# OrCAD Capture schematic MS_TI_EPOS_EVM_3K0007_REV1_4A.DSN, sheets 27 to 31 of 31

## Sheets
27 Pg06: NAND Flash Memory: size C
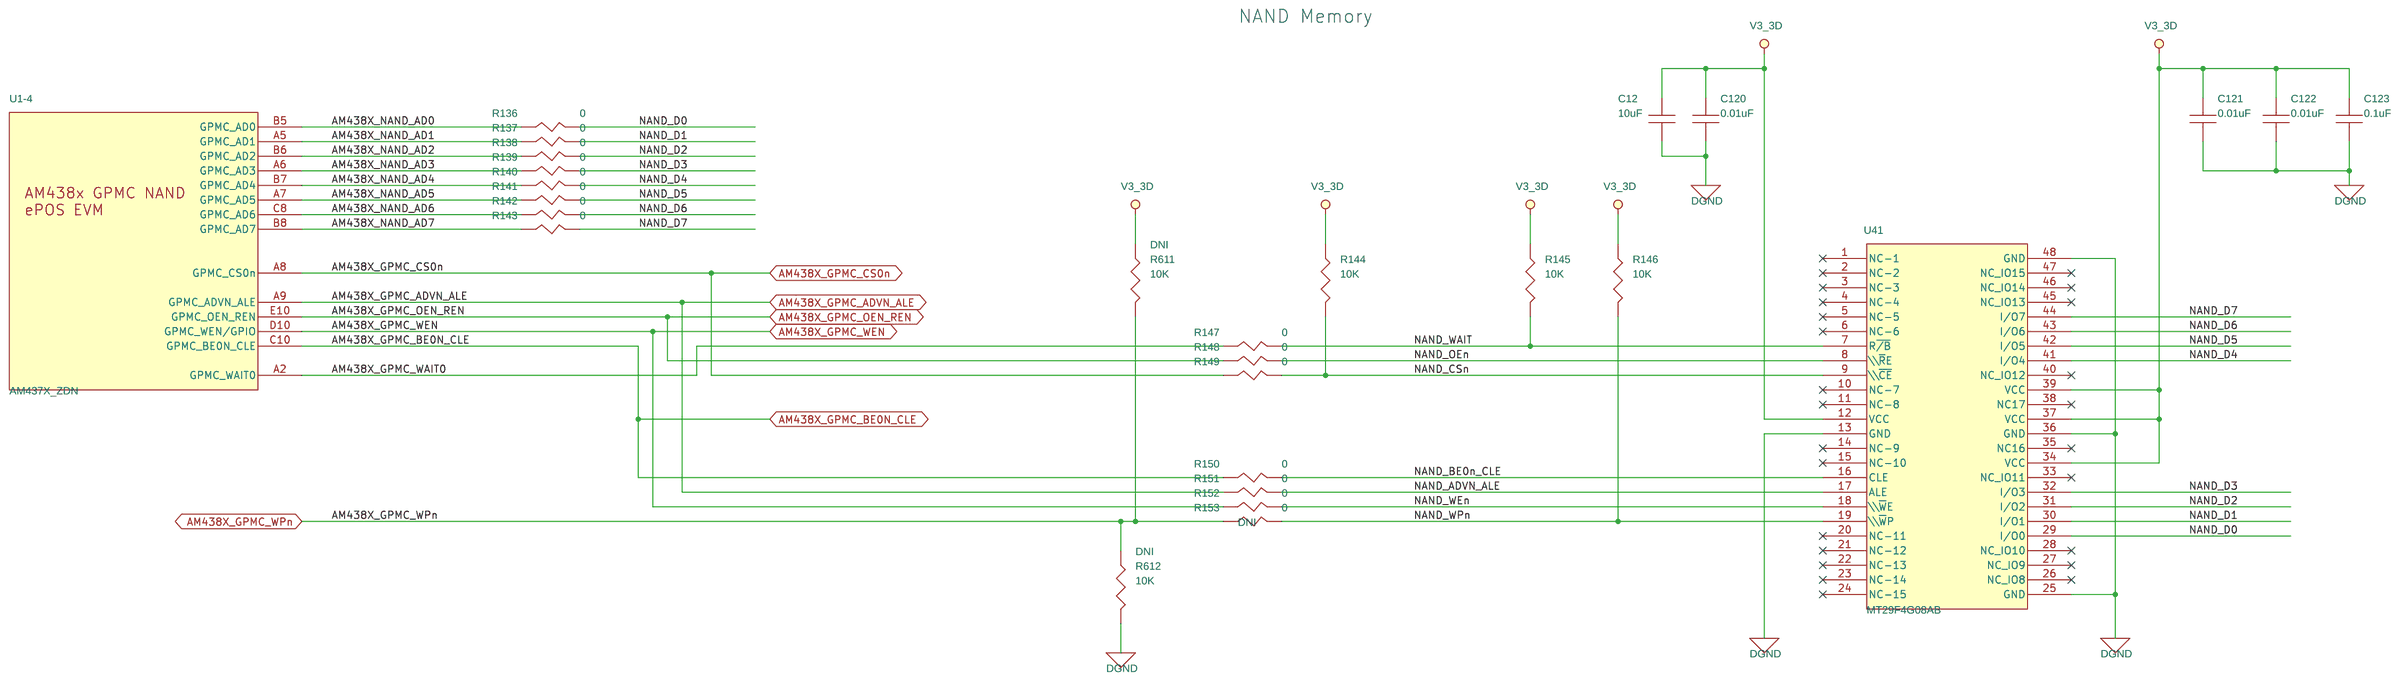
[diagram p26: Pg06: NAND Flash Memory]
28 Pg28: Unused pins/GPIO: size C
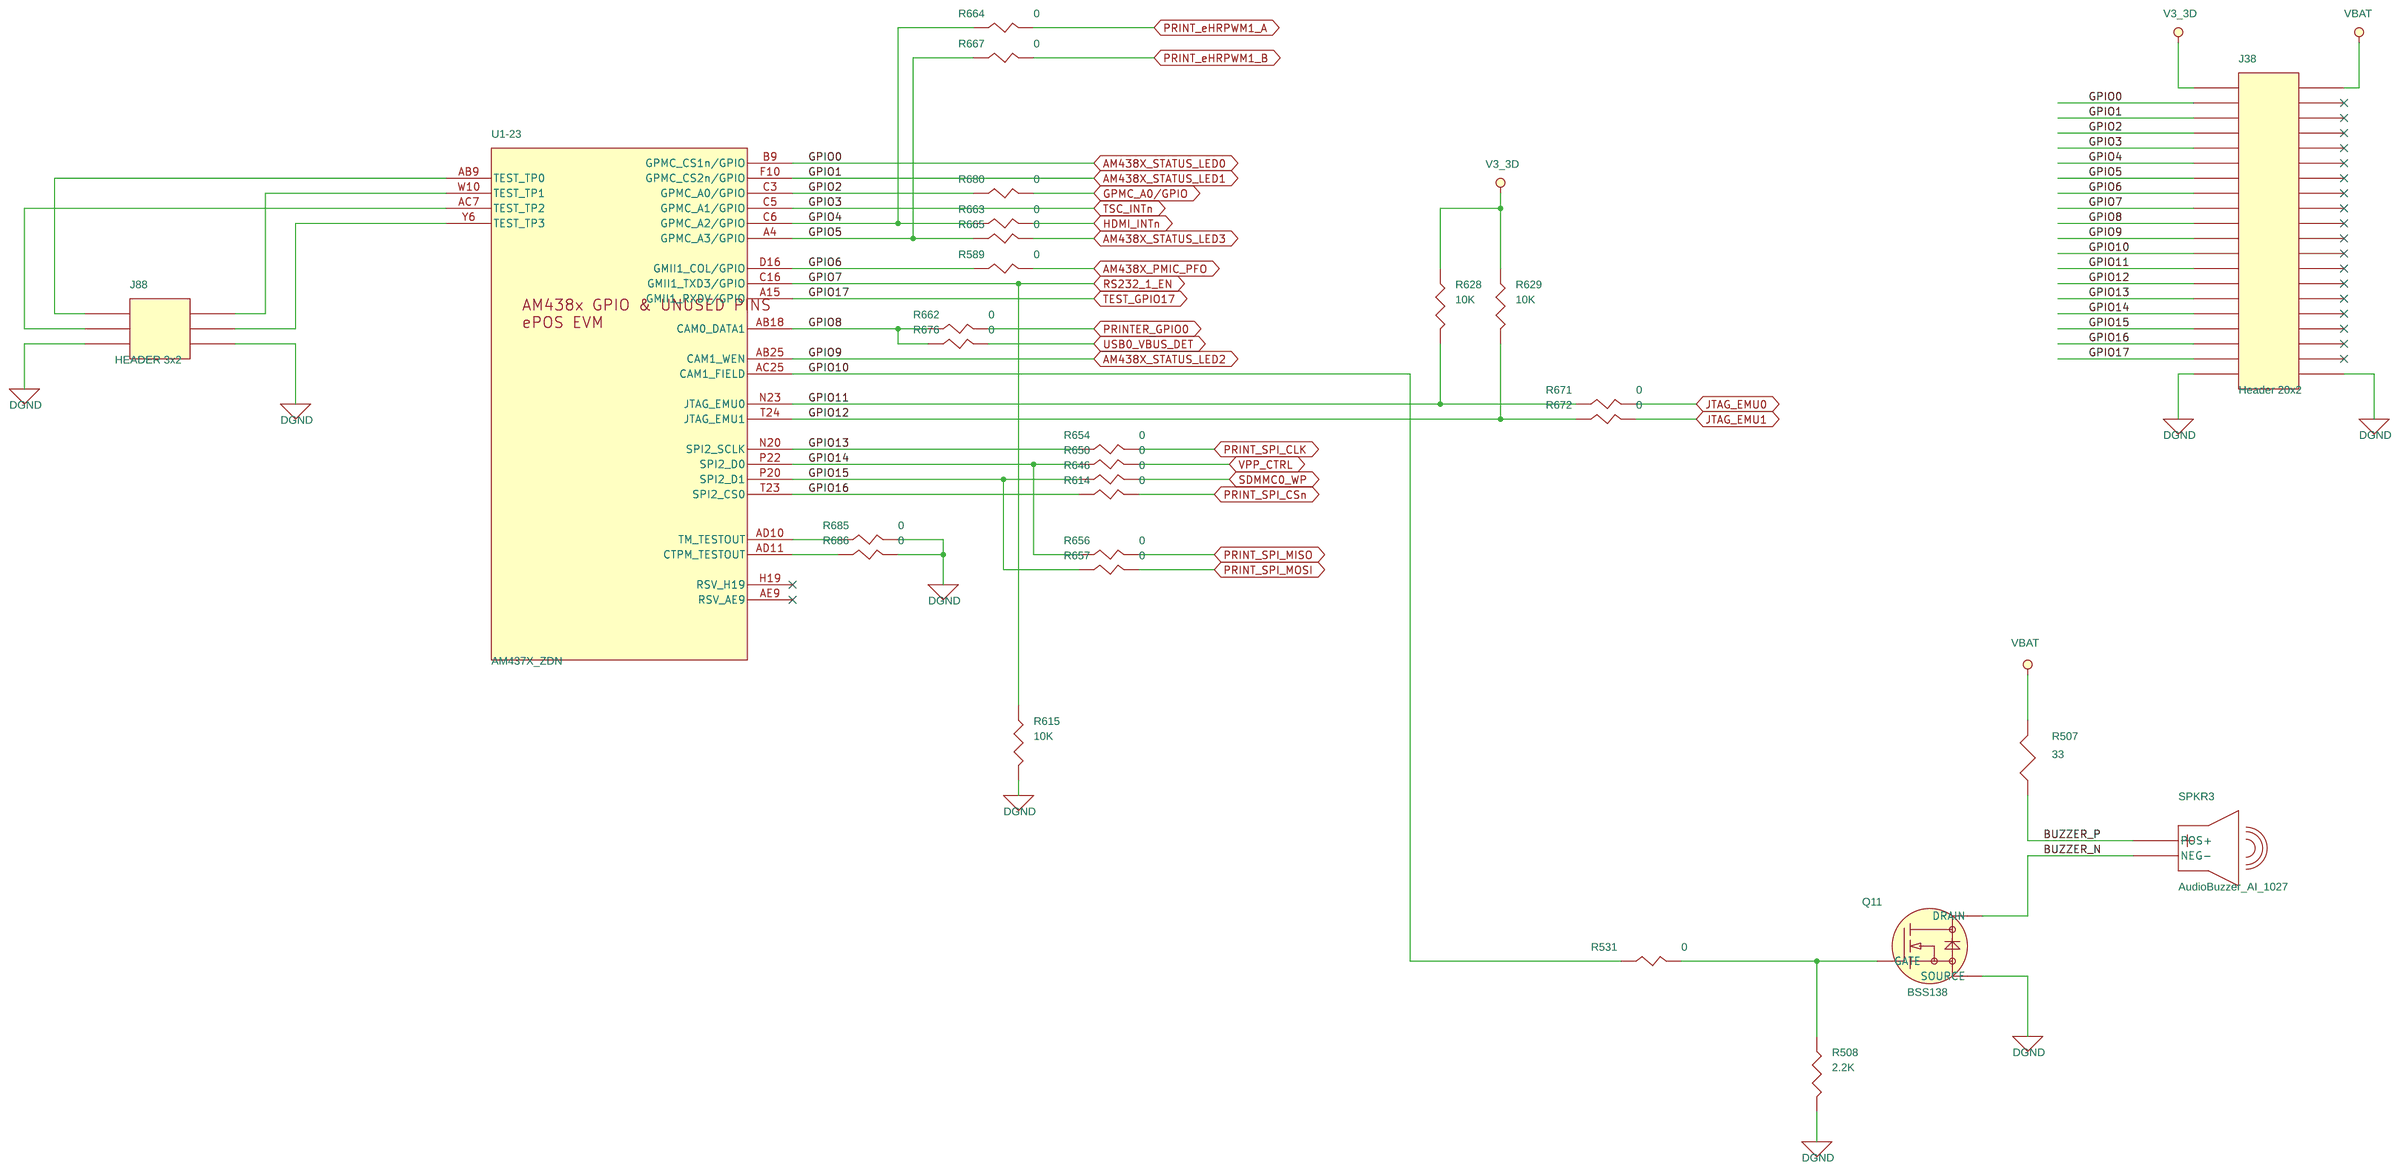
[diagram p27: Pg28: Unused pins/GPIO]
29 Pg31: Hardware schematics
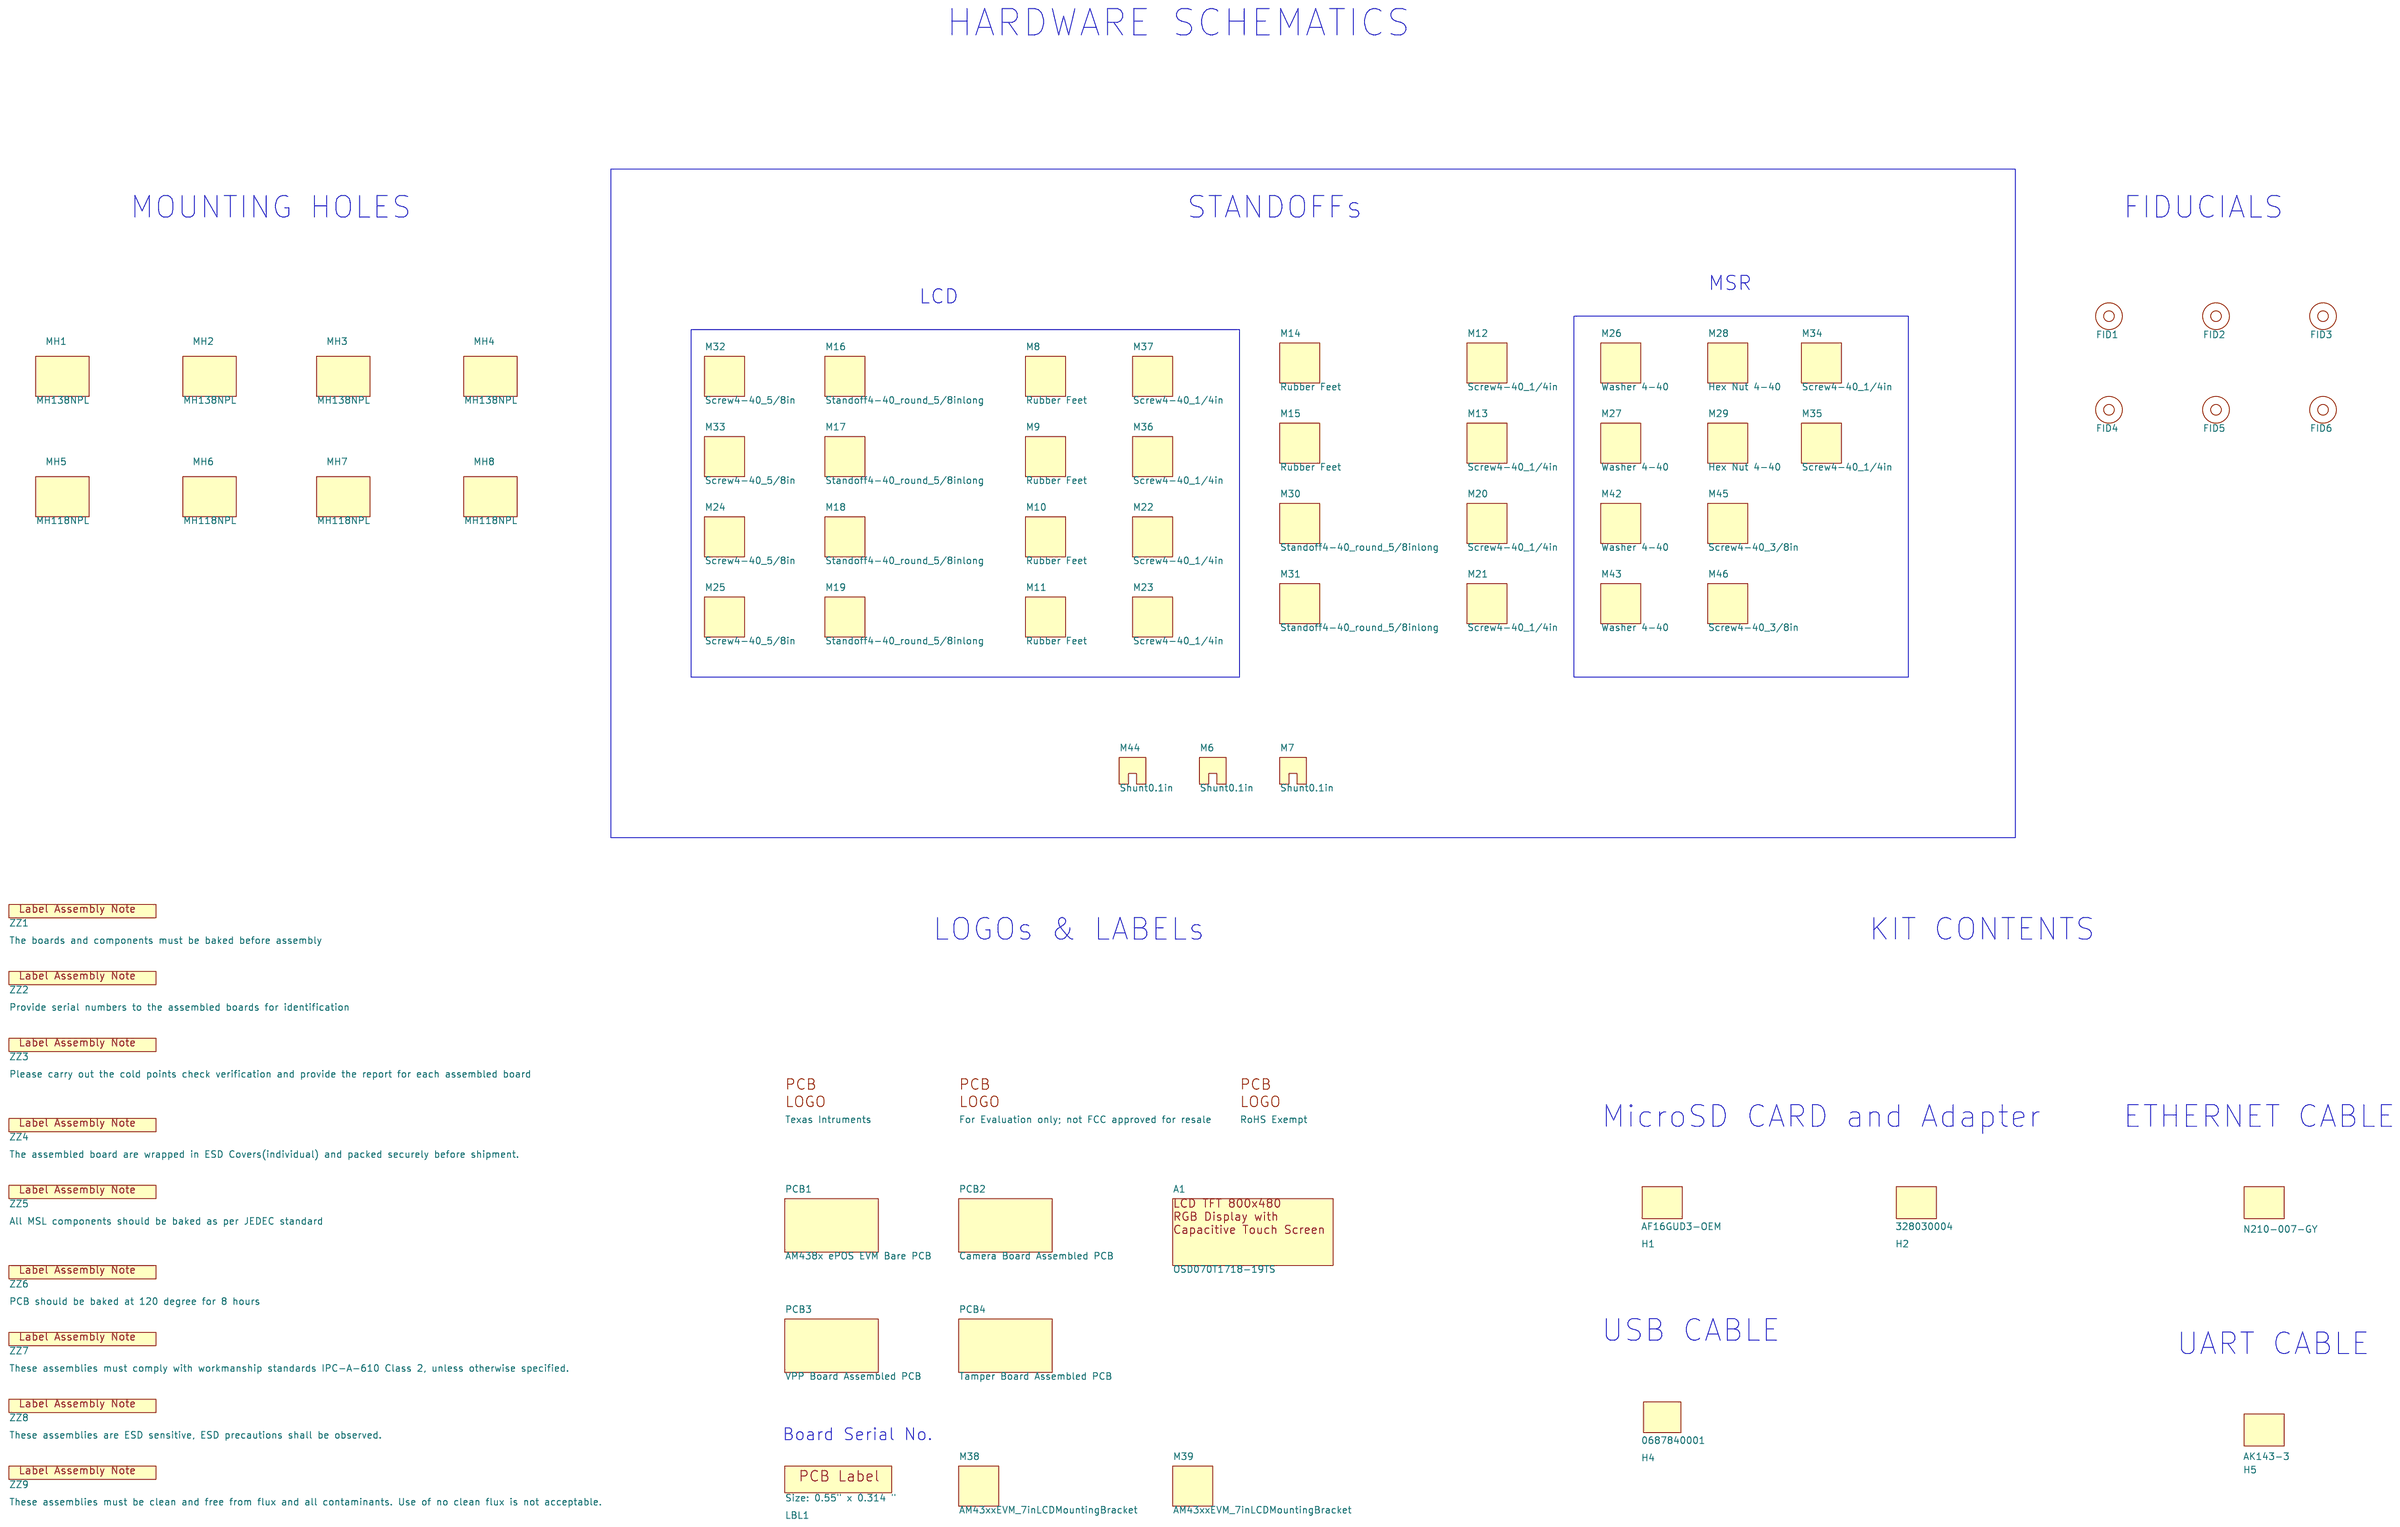
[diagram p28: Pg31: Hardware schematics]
30 Pg04: Power Supply - PMIC: size C
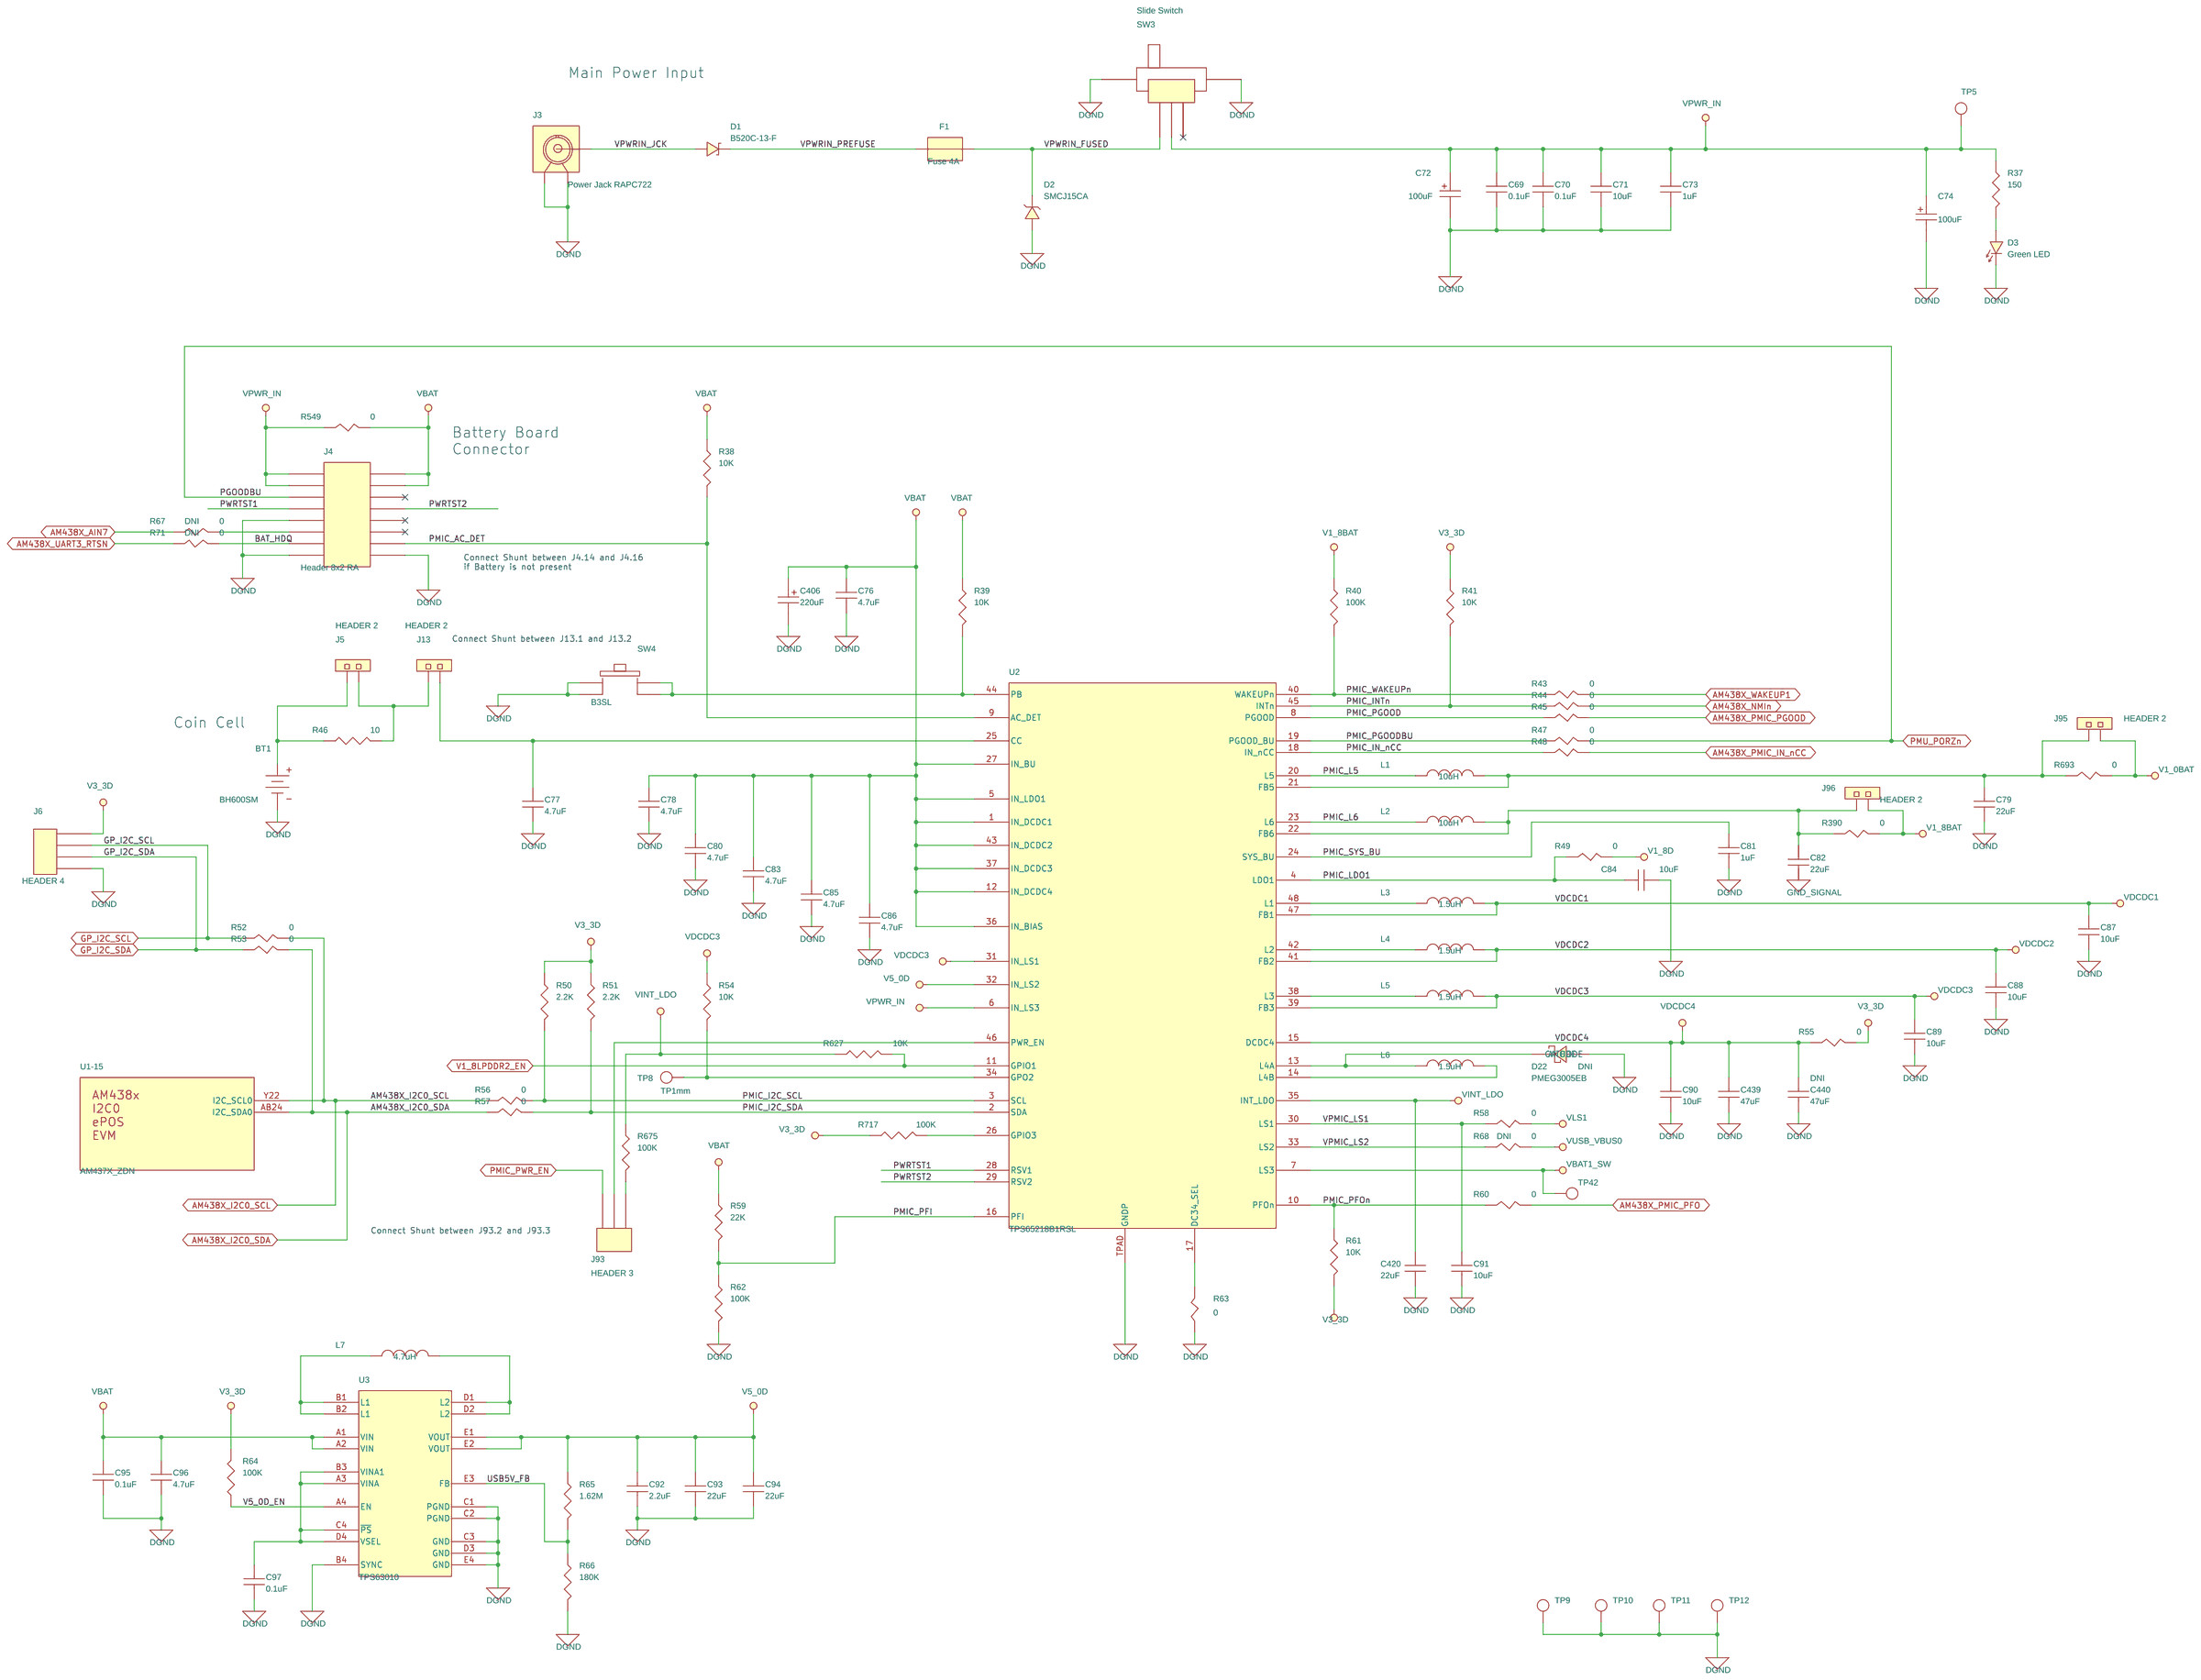
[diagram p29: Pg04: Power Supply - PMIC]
31 Pg02: Processor subsystem/RTC: size C
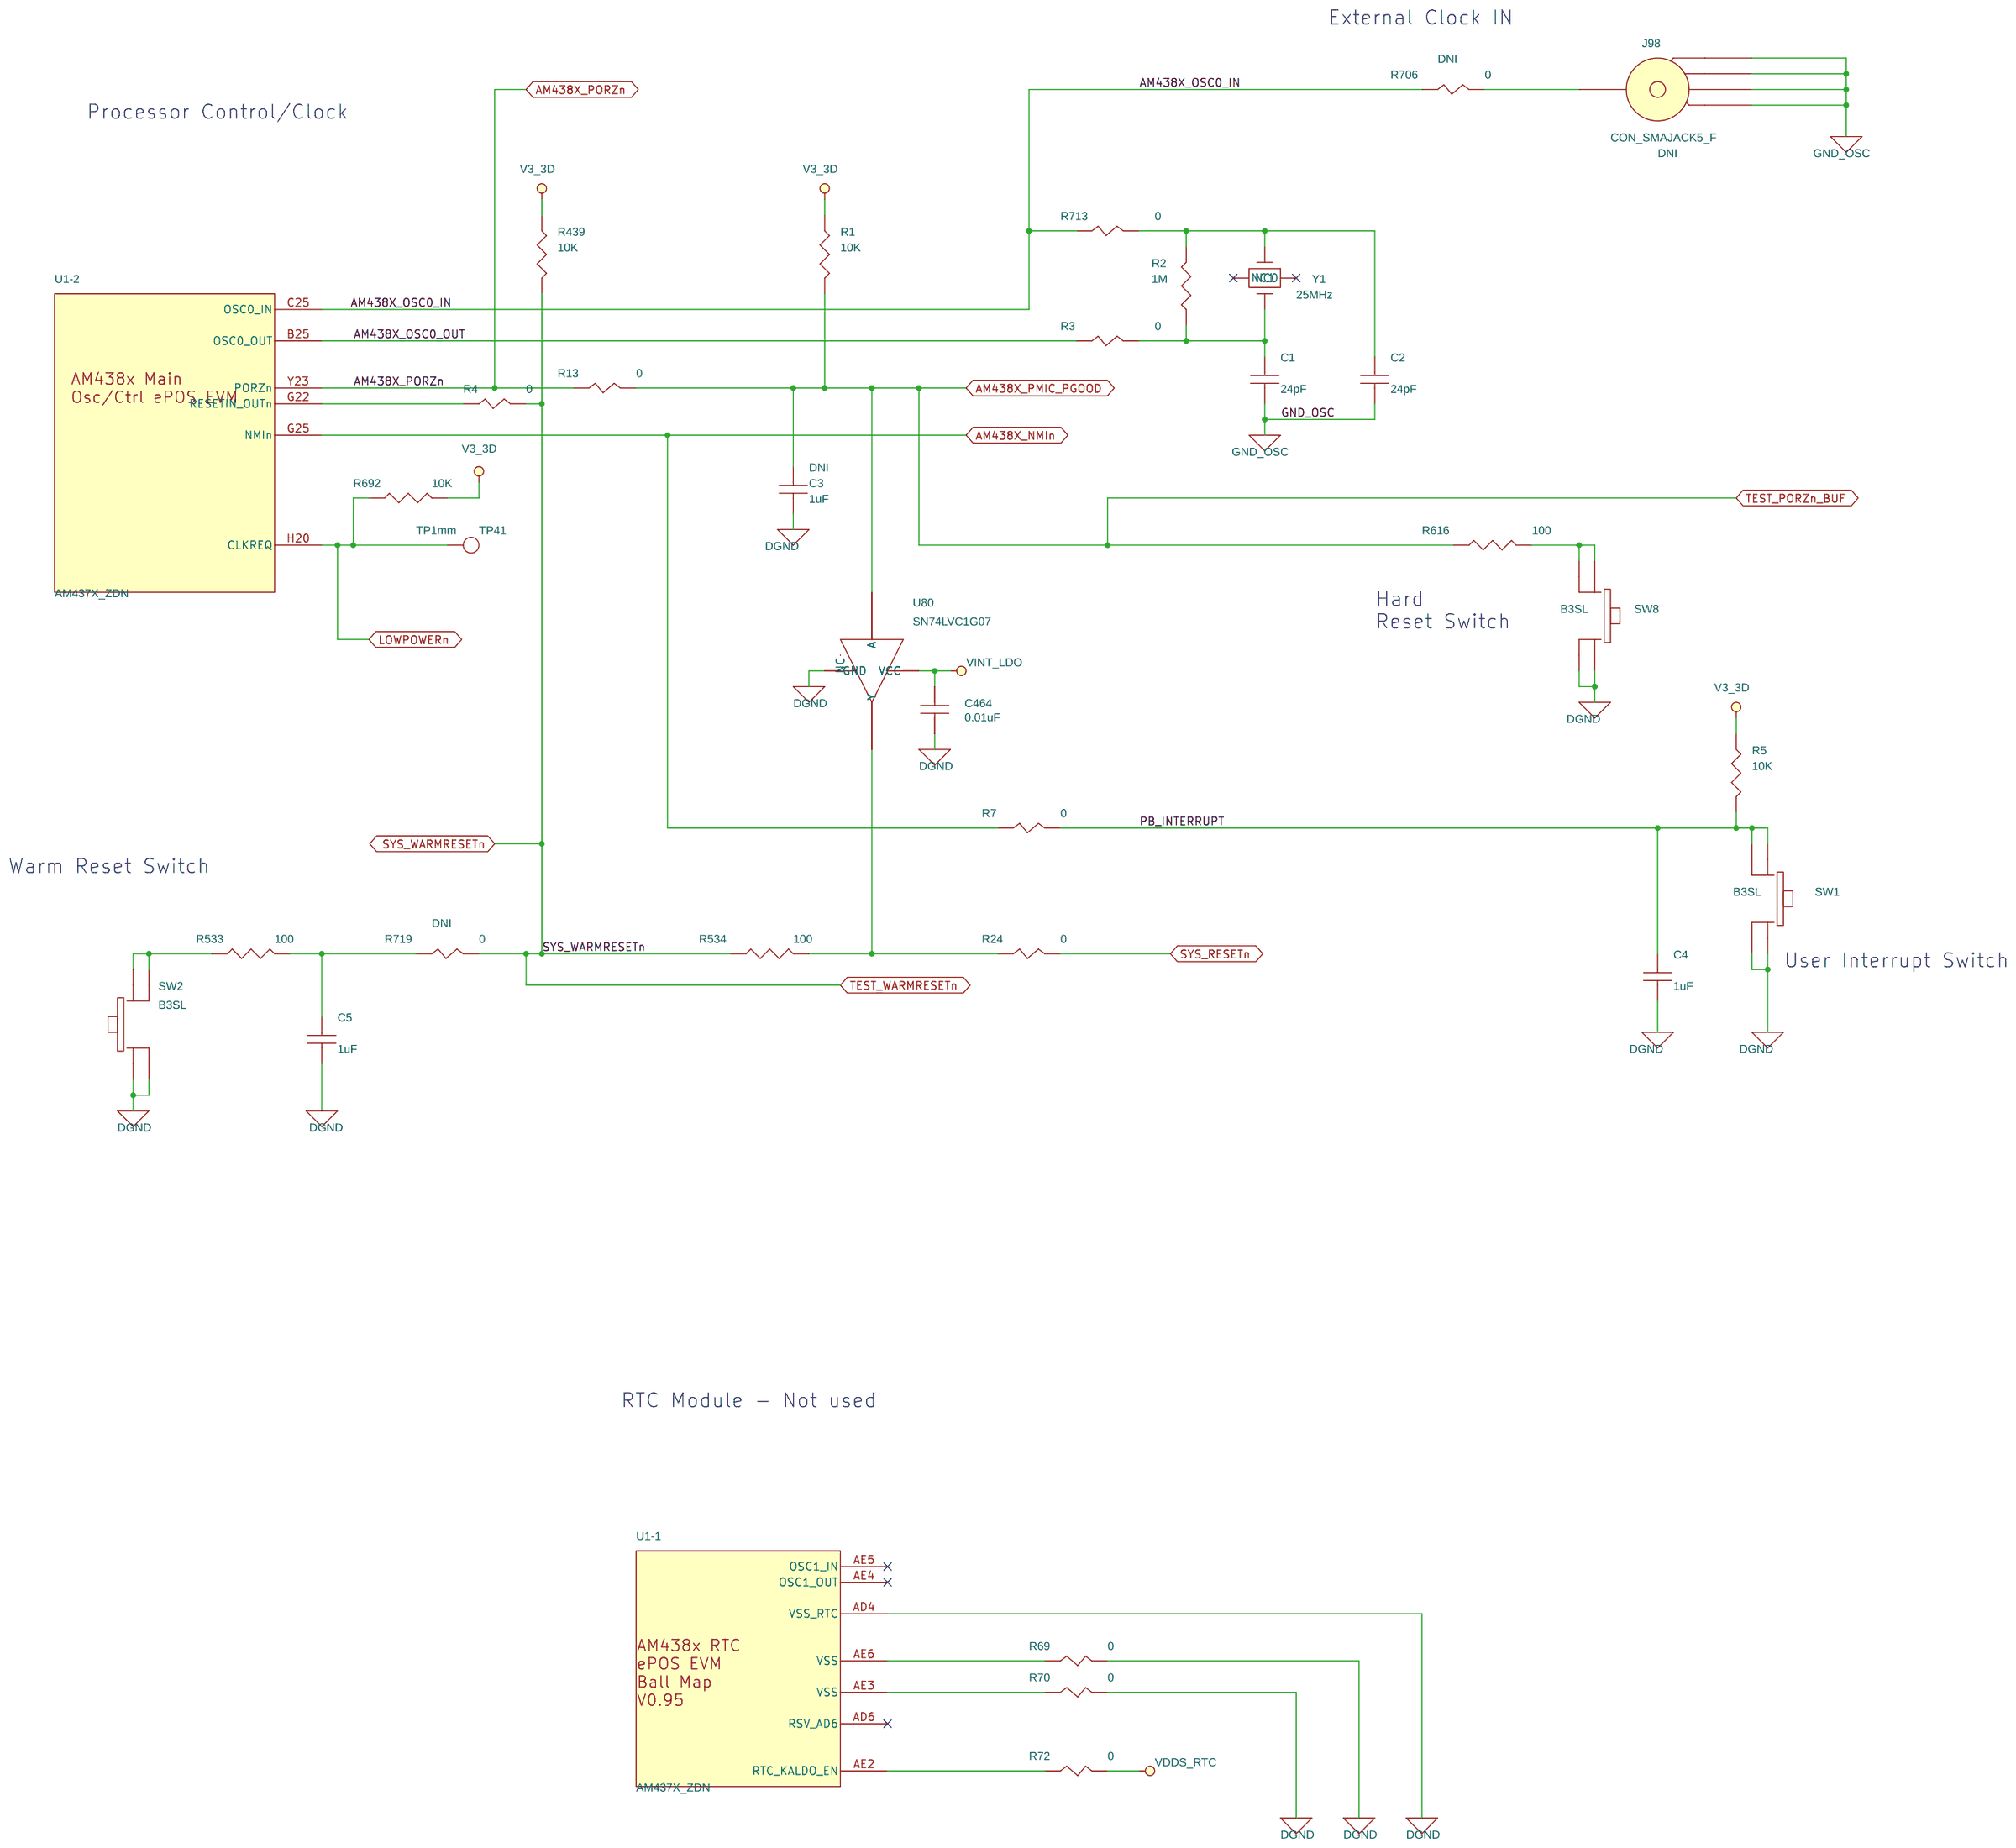
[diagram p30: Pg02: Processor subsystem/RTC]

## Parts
sheet Pg02: Processor subsystem/RTC
C1  24pF  [SM-7351-CAP-0402]
C2  24pF  [SM-7351-CAP-0402]
C3  1uF  [SM-7351-CAP-0402]
C4  1uF  [SM-7351-CAP-0402]
C5  1uF  [SM-7351-CAP-0402]
C464  0.01uF  [SM-7351-CAP-0402]
J98  CON_SMAJACK5_F  [CON_SMAJACK5_221789-1_S_S_T]
R1  10K  [SM-7351-RES-0402]
R2  1M  [SM-7351-RES-0402]
R3  0  [SM-7351-RES-0402]
R4  0  [SM-7351-RES-0402]
R5  10K  [SM-7351-RES-0402]
R7  0  [SM-7351-RES-0402]
R13  0  [SM-7351-RES-0402]
R24  0  [SM-7351-RES-0402]
R69  0  [SM-7351-RES-0402]
R70  0  [SM-7351-RES-0402]
R72  0  [SM-7351-RES-0402]
R439  10K  [SM-7351-RES-0402]
R533  100  [SM-7351-RES-0402]
R534  100  [SM-7351-RES-0402]
R616  100  [SM-7351-RES-0402]
R692  10K  [SM-7351-RES-0402]
R706  0  [SM-7351-RES-0402]
R713  0  [SM-7351-RES-0402]
R719  0  [SM-7351-RES-0402]
SW1  B3SL  [SW_B3SL-1022P]
SW2  B3SL  [SW_B3SL-1022P]
SW8  B3SL  [SW_B3SL-1022P]
TP41  TP1mm  [tp_smd1mmcircle]
U80  SN74LVC1G07  [SC70-5-43M]
Y1  25MHz  [XTAL2x3-30m]
sheet Pg04: Power Supply - PMIC
BT1  BH600SM  [bh600sm]
C69  0.1uF  [SM-7351-CAP-0402]
C70  0.1uF  [SM-7351-CAP-0402]
C71  10uF  [SM-7351-CAP-0805]
C72  100uF  [SM-7351-CAP-smdcan]
C73  1uF  [SM-7351-CAP-0603]
C74  100uF  [SM-7351-CAP-smdcan]
C76  4.7uF  [SM-7351-CAP-0603]
C77  4.7uF  [SM-7351-CAP-0603]
C78  4.7uF  [SM-7351-CAP-0603]
C79  22uF  [SM-7351-CAP-0603]
C80  4.7uF  [SM-7351-CAP-0603]
C81  1uF  [SM-7351-CAP-0402]
C82  22uF  [SM-7351-CAP-0603]
C83  4.7uF  [SM-7351-CAP-0603]
C84  10uF  [SM-7351-CAP-0805]
C85  4.7uF  [SM-7351-CAP-0603]
C86  4.7uF  [SM-7351-CAP-0603]
C87  10uF  [SM-7351-CAP-0805]
C88  10uF  [SM-7351-CAP-0805]
C89  10uF  [SM-7351-CAP-0805]
C90  10uF  [SM-7351-CAP-0805]
C91  10uF  [SM-7351-CAP-0805]
C92  2.2uF  [SM-7351-CAP-0402]
C93  22uF  [SM-7351-CAP-0805]
C94  22uF  [SM-7351-CAP-0805]
C95  0.1uF  [SM-7351-CAP-0402]
C96  4.7uF  [SM-7351-CAP-0603]
C97  0.1uF  [SM-7351-CAP-0402]
C406  220uF  [smd7343-122m]
C420  22uF  [SM-7351-CAP-0805]
C439  47uF  [SM-7351-CAP-1206]
C440  47uF  [SM-7351-CAP-1206]
D1  B520C-13-F  [B520C-13-F]
D2  SMCJ15CA  [SMCJ15CA]
D3  Green LED  [sm_led_0805]
D22  PMEG3005EB  [DIO_SOD523]
F1  Fuse 4A  [smdfuseblk]
J3  Power Jack RAPC722  [RAPC712]
J4  Header 8x2 RA  [HDR2X8RA-201M]
J5  HEADER 2  [header_2x1]
J6  HEADER 4  [HDR1x4-330M]
J13  HEADER 2  [header_2x1]
J93  HEADER 3  [header_3x1]
J95  HEADER 2  [header_2x1]
J96  HEADER 2  [header_2x1]
L1  10uH  [ind-mlz2012-57m]
L2  10uH  [ind-mlz2012-57m]
L3  1.5uH  [IND_SPM3012T]
L4  1.5uH  [IND_SPM3012T]
L5  1.5uH  [IND_SPM3012T]
L6  1.5uH  [IND_SPM3012T]
L7  4.7uH  [smd_slf7055t]
R37  150  [SM-7351-RES-0402]
R38  10K  [SM-7351-RES-0402]
R39  10K  [SM-7351-RES-0402]
R40  100K  [SM-7351-RES-0402]
R41  10K  [SM-7351-RES-0402]
R43  0  [SM-7351-RES-0402]
R44  0  [SM-7351-RES-0402]
R45  0  [SM-7351-RES-0402]
R46  10  [SM-7351-RES-0402]
R47  0  [SM-7351-RES-0402]
R48  0  [SM-7351-RES-0402]
R49  0  [SM-7351-RES-0603]
R50  2.2K  [sm-7351-res-0402]
R51  2.2K  [sm-7351-res-0402]
R52  0  [SM-7351-RES-0402]
R53  0  [SM-7351-RES-0402]
R54  10K  [SM-7351-RES-0402]
R55  0  [SM-7351-RES-0603]
R56  0  [SM-7351-RES-0402]
R57  0  [SM-7351-RES-0402]
R58  0  [SM-7351-RES-0402]
R59  22K  [SM-7351-RES-0402]
R60  0  [SM-7351-RES-0402]
R61  10K  [SM-7351-RES-0402]
R62  100K  [SM-7351-RES-0402]
R63  0  [SM-7351-RES-0402]
R64  100K  [SM-7351-RES-0402]
R65  1.62M  [SM-7351-RES-0402]
R66  180K  [SM-7351-RES-0402]
R67  0  [SM-7351-RES-0402]
R68  0  [SM-7351-RES-0402]
R71  0  [SM-7351-RES-0402]
R390  0  [SM-7351-RES-0603]
R549  0  [SM-7351-RES-1210]
R627  10K  [SM-7351-RES-0402]
R675  100K  [SM-7351-RES-0402]
R693  0  [SM-7351-RES-0603]
R717  100K  [SM-7351-RES-0402]
SW3  Slide Switch  [TH_SW_T551101]
SW4  B3SL  [SW_B3SL-1022P]
TP5  TP  [TH_TP_5002]
TP8  TP1mm  [tp_smd1mmcircle]
TP9  TP  [TH_TP_5002]
TP10  TP  [TH_TP_5002]
TP11  TP  [TH_TP_5002]
TP12  TP  [TH_TP_5002]
TP42  TP  [TH_TP_5002]
U2  TPS65218B1RSL  [qfn6x6-48-39m]
U3  TPS63010  [u_20_dsbga]
sheet Pg06: NAND Flash Memory
C12  10uF  [SM-7351-CAP-0805]
C120  0.01uF  [SM-7351-CAP-0402]
C121  0.01uF  [SM-7351-CAP-0402]
C122  0.01uF  [SM-7351-CAP-0402]
C123  0.1uF  [SM-7351-CAP-0402]
R136  0  [SM-7351-RES-0402]
R137  0  [SM-7351-RES-0402]
R138  0  [SM-7351-RES-0402]
R139  0  [SM-7351-RES-0402]
R140  0  [SM-7351-RES-0402]
R141  0  [SM-7351-RES-0402]
R142  0  [SM-7351-RES-0402]
R143  0  [SM-7351-RES-0402]
R144  10K  [SM-7351-RES-0402]
R145  10K  [SM-7351-RES-0402]
R146  10K  [SM-7351-RES-0402]
R147  0  [SM-7351-RES-0402]
R148  0  [SM-7351-RES-0402]
R149  0  [SM-7351-RES-0402]
R150  0  [SM-7351-RES-0402]
R151  0  [SM-7351-RES-0402]
R152  0  [SM-7351-RES-0402]
R153  0  [SM-7351-RES-0402]
R611  10K  [SM-7351-RES-0402]
R612  10K  [SM-7351-RES-0402]
U41  MT29F4G08AB  [skt-tsop48sm]
sheet Pg26: Keypad/LED's
U1  AM437X_ZDN  [AM437X_ZDN]  (sections -1,-10,-11,-12,-13,-14,-15,-16,-17,-18,-19,-2,-20,-21,-22,-23,-24,-25,-26,-27,-3,-4,-5,-6,-7,-8,-9)
sheet Pg28: Unused pins/GPIO
J38  Header 20x2  [HDR2X20-330M]
J88  HEADER 3x2  [hdr2x3-330m]
Q11  BSS138  [SOT23-3]
R507  33  [SM-7351-RES-0402]
R508  2.2K  [sm-7351-res-0402]
R531  0  [SM-7351-RES-0402]
R589  0  [SM-7351-RES-0402]
R614  0  [SM-7351-RES-0402]
R615  10K  [SM-7351-RES-0402]
R628  10K  [SM-7351-RES-0402]
R629  10K  [SM-7351-RES-0402]
R646  0  [SM-7351-RES-0402]
R650  0  [SM-7351-RES-0402]
R654  0  [SM-7351-RES-0402]
R656  0  [SM-7351-RES-0402]
R657  0  [SM-7351-RES-0402]
R662  0  [SM-7351-RES-0402]
R663  0  [SM-7351-RES-0402]
R664  0  [SM-7351-RES-0402]
R665  0  [SM-7351-RES-0402]
R667  0  [SM-7351-RES-0402]
R671  0  [SM-7351-RES-0402]
R672  0  [SM-7351-RES-0402]
R676  0  [SM-7351-RES-0402]
R680  0  [SM-7351-RES-0402]
R685  0  [SM-7351-RES-0402]
R686  0  [SM-7351-RES-0402]
SPKR3  AudioBuzzer_AI_1027  [spkr_ai_1027]
sheet Pg31: Hardware schematics
A1  OSD070T1718-19TS  [DNP]
FID1  Fiducial  [Fiducial10-20]
FID2  Fiducial  [Fiducial10-20]
FID3  Fiducial  [Fiducial10-20]
FID4  Fiducial  [Fiducial10-20]
FID5  Fiducial  [Fiducial10-20]
FID6  Fiducial  [Fiducial10-20]
H1  AF16GUD3-OEM  [Keystone_1902C]
H2  328030004  [Keystone_1902C]
H3  N210-007-GY  [Keystone_1902C]
H4  0687840001  [Keystone_1902C]
H5  AK143-3  [Keystone_1902C]
LBL1  Size: 0.55" x 0.314 "  [Label_650x200]
LOGO1  Texas Intruments  [TI_Stacked_Overlay_Small]
LOGO3  For Evaluation only; not FCC approved for resale  [FCC_disclaimer]
LOGO4  RoHS Exempt  [TI_Stacked_Overlay_Small]
M6  Shunt0.1in  [DNP]
M7  Shunt0.1in  [DNP]
M8  Rubber Feet  [DNP]
M9  Rubber Feet  [DNP]
M10  Rubber Feet  [DNP]
M11  Rubber Feet  [DNP]
M12  Screw4-40_1/4in  [DNP]
M13  Screw4-40_1/4in  [DNP]
M14  Rubber Feet  [DNP]
M15  Rubber Feet  [DNP]
M16  Standoff4-40_round_5/8inlong  [DNP]
M17  Standoff4-40_round_5/8inlong  [DNP]
M18  Standoff4-40_round_5/8inlong  [DNP]
M19  Standoff4-40_round_5/8inlong  [DNP]
M20  Screw4-40_1/4in  [DNP]
M21  Screw4-40_1/4in  [DNP]
M22  Screw4-40_1/4in  [DNP]
M23  Screw4-40_1/4in  [DNP]
M24  Screw4-40_5/8in  [DNP]
M25  Screw4-40_5/8in  [DNP]
M26  Washer 4-40  [DNP]
M27  Washer 4-40  [DNP]
M28  Hex Nut 4-40  [DNP]
M29  Hex Nut 4-40  [DNP]
M30  Standoff4-40_round_5/8inlong  [DNP]
M31  Standoff4-40_round_5/8inlong  [DNP]
M32  Screw4-40_5/8in  [DNP]
M33  Screw4-40_5/8in  [DNP]
M34  Screw4-40_1/4in  [DNP]
M35  Screw4-40_1/4in  [DNP]
M36  Screw4-40_1/4in  [DNP]
M37  Screw4-40_1/4in  [DNP]
M38  AM43xxEVM_7inLCDMountingBracket  [DNP]
M39  AM43xxEVM_7inLCDMountingBracket  [DNP]
M42  Washer 4-40  [DNP]
M43  Washer 4-40  [DNP]
M44  Shunt0.1in  [DNP]
M45  Screw4-40_3/8in  [DNP]
M46  Screw4-40_3/8in  [DNP]
MH1  MH138NPL
MH2  MH138NPL
MH3  MH138NPL
MH4  MH138NPL
MH5  MH118NPL
MH6  MH118NPL
MH7  MH118NPL
MH8  MH118NPL
PCB1  AM438x ePOS EVM Bare PCB  [DNP]
PCB2  Camera Board Assembled PCB  [DNP]
PCB3  VPP Board Assembled PCB
PCB4  Tamper Board Assembled PCB
ZZ1  The boards and components must be baked before assembly  [AssemblyNoteLabel]
ZZ2  Provide serial numbers to the assembled boards for identification  [AssemblyNoteLabel]
ZZ3  Please carry out the cold points check verification and provide the report for each assembled board  [AssemblyNoteLabel]
ZZ4  The assembled board are wrapped in ESD Covers(individual) and packed securely before shipment.  [AssemblyNoteLabel]
ZZ5  All MSL components should be baked as per JEDEC standard  [AssemblyNoteLabel]
ZZ6  PCB should be baked at 120 degree for 8 hours  [AssemblyNoteLabel]
ZZ7  These assemblies must comply with workmanship standards IPC-A-610 Class 2, unless otherwise specified.  [AssemblyNoteLabel]
ZZ8  These assemblies are ESD sensitive, ESD precautions shall be observed.  [AssemblyNoteLabel]
ZZ9  These assemblies must be clean and free from flux and all contaminants. Use of no clean flux is not acceptable.  [AssemblyNoteLabel]

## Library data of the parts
C1 C2 = 1C_24pFCapacitor50V5%SMD0402: Cost100: 0.16; Cost10K: 0; Mistral Part No: M120016080001
C3 = 1C_1uFCapacitor10V10%0402: Cost100: 0.33; Cost10K: 0.2; Loading: DNI; Mistral Part No: 120014050010-R
C4 C5 C81 = 1C_1uFCapacitor10V10%0402: Cost100: 0.33; Cost10K: 0.2; Mistral Part No: 120014050010-R
C120-C122 C464 = 1C_0.01uFCapacitor16V10%0402: Cost100: 0; Cost10K: 0.01; Mistral Part No: 120009030032-R
J98 = CON_SMAJACK5_F: Chkd/date: NAVEED/031014; Composition: Updated drill size; Crtd /date: VASANTHA/240714; Custom_Duty: 24%; Customs_HS_Code: 85369090; DescriptiveText: CON SMA JACK 5POS FEMALE ST TH; Distributor_name: DIGIKEY; Distributor_part_number: ACX1962-ND; Loading: DNI; Mfr: TYCO ELECTRONICS; MfrNum: 221789-1; Mistral Part No: 150011080043-R; Package: THRU HOLE; PartName: 221789-1; Part_type: CONNECTOR\JACK; Project: DC_MIST_RF-TEST CARD; RoHS: RoHS; Temperature: NA; Tolerance: NA; Vendor: Digikey; Voltage: NA; Wattage: NA; Weight: NA; Datasheet: Y:\MIS_DATABASE\DATASHEETS\CONNECTORS\132134-15.PDF
R1 R5 R38 R39 R41 R54 R61 R144-R146 R439 R615 R627-R629 R692 = 1R_10KOhmResistor1_16W0402: Cost10K: 0; Mistral Part No: 110011060003-R
R2 = 1MOhmResistor1_16W0402: Cost100: 0.01; Cost10K: 0; Mistral Part No: 110014060045-R
R3 R4 R7 R13 R24 R43-R45 R47 R48 R52 R53 R56-R58 R60 R63 R69 R70 R72 R136-R143 R147-R152 R531 R589 R614 R646 R650 R654 R656 R657 R662-R665 R667 R671 R672 R676 R680 R685 R686 R713 = 1R_ZeroOhmResistor1_16W0402: Mistral Part No: 110014100008-R
R533 R534 R616 = 1R_100ohm1_16W1%SMD0402: Cost100: 0.01; Cost10K: 0; Mistral Part No: 110014060039-R
R67 R68 R71 R153 R706 R719 = 1R_ZeroOhmResistor1_16W0402: Loading: DNI; Mistral Part No: 110014100008-R
SW1 SW2 SW4 SW8 = 2W_Switch_Pushbuttonsmd: Cost100: 0.34; Cost10K: 0.33; Mistral Part No: 130014060032-R
TP8 TP41 = 2H_Testpoint_SMD1mmCircle
U80 = 1A_SN74LVC1G07: MfrNum: SN74LVC1G07DCKR; Mistral Part No: 141014060023-R
Y1 = 1Y_Crystal25MHzSCM: Cost100: 0.9; Mistral Part No: M130016080008
BT1 = 1P_BatteryCR1632Holder: Mistral Part No: 130014060033-R
C69 C70 C95 C97 C123 = 1C_0.1uFCapacitor16V10%0402: Cost10K: 0.01; MfrNum: C0402C104K4RACTU; Mistral Part No: 120009030060-R
C12 C71 C84 C87-C91 = 1C_10uFCapacitor16V10%0805: Cost10K: 0.04; Mistral Part No: 120011040011-R
C72 C74 = 1C_100uFCapacitor16V20%ElecPoly: Mistral Part No: 120014060011-R
C73 = 1C_1uFCapacitor50V10%0603: Cost10K: 0.04; Mistral Part No: M120016080002
C76-C78 C80 C83 C85 C86 C96 = 1C_4.7uFCapacitor16V10%0603: Cost100: 0.01; Cost10K: 0; Mistral Part No: 120011050004-R
C79 C82 = 1C_22uFCapacitor6.3V20%0603: Cost10K: 0.04; Mistral Part No: M120016080003
C92 = 1C_2.2uFCapacitor6.3V20%X5R0402: Cost100: 0.5; Cost10K: 0.05; Mistral Part No: 120009030281-R
C93 C94 C420 = 1C_22uFCapacitor16V10%0805: Mistral Part No: 120014060009-R
C406 = 1C_220uFCapacitor16V10%Tantalum: MfrNum: T491D227K016AT; Mistral Part No: 120014060012-R
C439 = 1C_47uFCapacitor16V20%1206: MfrNum: C3216X5R1C476M160AB; Mistral Part No: 120011060001-R
C440 = 1C_47uFCapacitor16V20%1206: Loading: DNI; MfrNum: C3216X5R1C476M160AB; Mistral Part No: 120011060001-R
D1 = 1E_Diode_5ARect: Cost10K: 0.52; Mistral Part No: 130009030175-R
D2 = 1E_Diode_SMCJ15CA: Cost10K: 0.41; Mistral Part No: 130009030286-R
D3 = 1F_LED_Green: Cost100: 0.08; Cost10K: 0.03; Mistral Part No: 130014050065-R
D22 = DIODE_SCHOTTKY: DIODE SCHOTTKY 30V 0.5A SOD523; Chkd/date: VASANTHA/310816; Crtd /date: VASANTHA/310816; Custom_Duty: 15%; Customs_HS_Code: 85412900; DescriptiveText: DIODE SCHOTTKY 30V 0.5A SOD523; Distributor_name: DIGIKEY; Distributor_part_number: 568-7397-1-ND; Loading: DNI; Mfr: NXP SEMICONDUCTOR; Mfr_name: NXP SEMICONDUCTOR; Mistral Part No: 130016080038-R; Package: SOD523; Part_type: DIODE\SCHOTTKY; Project: EPOS_EVM; RoHS: RoHS; Temperature: -65°C+150°C; Tolerance: NA; Voltage: 30V; Wattage: NA; Weight: NA; Datasheet: Y:\MIS_DATABASE\DATASHEETS\DISCRETES\DIODES\PMEG3005EB.PDF
F1 = 1P_Fuse_4A: Cost10K: 2.09; Mistral Part No: 130010060001-R
J3 = 2J_Conn_PwrJack_RAPC712: Cost100: 0.9; MfrNum: RAPC722X; Mistral Part No: 150009030334-R
J4 = 2H_Header8x2pin_RA: Mistral Part No: 150014050021-R
J5 J13 J95 J96 = 2H_Header_2x1: Cost100: 0.01; Cost10K: 0.25; Mistral Part No: M150016080001
J6 = 2H_Header_4x1: Mistral Part No: 150014050025-R
J93 = 2H_Header_3x1: Cost100: 0.26; Cost10K: 0.26; Mistral Part No: M150016080010
L1 L2 = 1L_10uHInductor20%110mAsmd: Cost10K: 0.58; MfrNum: MLZ2012N100LT000; Mistral Part No: 130014050064-R
L3-L6 = 1L_1.5uHInductor20%2.8Asmd: Cost10K: 0.58; Mistral Part No: 130014050063-R
L7 = 1L_4.7uHInductor30%3.1Asmd: Cost10K: 0.34; Mistral Part No: 130014060035-R
R37 = 1R_150ohm1_16W1%SMD0402: Cost100: 0.01; Cost10K: 0; Mistral Part No: 110014060050-R
R40 R62 R64 R675 R717 = 1R_100KOhmResistor1_16W0402: Cost100: 0.01; Cost10K: 0; Mistral Part No: 110014060043-R
R46 = 1R_10ohm1_16W5%smd0402: Cost10K: 0; Mistral Part No: 110014060037-R
R49 R55 R390 R693 = 1R_ZeroOhmResistor1_16W0603: Cost10K: 0.05; Mistral Part No: 110014070017-R
R50 R51 R508 = 1R_2.2KOhmResistor1_16W0402: Cost100: 0.05; Cost10K: 0; Mistral Part No: 110014060053-R
R59 = 1R_22Kohm1_16W1%SMD0402: Cost100: 0; Cost10K: 0.02; Mistral Part No: 110009030525-P
R65 = 1R_1.62MOhmResistor1_16W0402: Cost100: 0.01; Cost10K: 0; Mistral Part No: 110011090001
R66 = 1R_180KOhmResistor1_16W0402: Cost100: 0.01; Cost10K: 0; Mistral Part No: 110014060040-R
R549 = 1R_ZeroOhmResistor1_2W1210: Cost10K: 0.05; Mistral Part No: 110009030079-P
SW3 = 2W_Switch_SlideRA_SPDT: Cost10K: 2.49; Mistral Part No: M130016080006
TP5 TP9-TP12 TP42 = 2H_TestPointThroughHole: Cost100: 0.16; Cost10K: 0.1; Mistral Part No: 160016120008-R
U2 = 1A_TPS65218: DescriptiveText: Power Management IC for AM437x SOC Mult Outputs-Rev B1 TPS65218B1RSL; MfrNum: TPS65218B1RSLR; Mistral Part No: 142016020007-R
U3 = 1A_TPS63010YFF: Cost100: 1.7; MfrNum: TPS63010YFFR; Mistral Part No: 142014060012-R
R611 R612 = 1R_10KOhmResistor1_16W0402: Cost10K: 0; Loading: DNI; Mistral Part No: 110011060003-R
U41 = 1A_MT29F4G08ABAE: MfrNum: MT29F4G08ABAEAWP:E; Mistral Part No: M141116080003
U1 = am438x_ZDN_ePOS_EVM_13: MfrNum: XAM4384CZDNA100S; Mistral Part No: 141214060001
J38 = 2H_Header20x2: Cost100: 0.8; Cost10K: 0.6; MfrNum: PEC20DAAN; Mistral Part No: 150014050027
J88 = 2H_Header3x2: Cost100: 0.62; Cost10K: 0.62; Mistral Part No: 150014050026-R
Q11 = 1Q_MOSFET_NChan_BSS138: Cost10K: 0.03; Mistral Part No: M130016080005
R507 = 1R_33ohmResistor1_16W5%0402: Cost100: 0.02; Cost10K: 0; Mistral Part No: 110009030699-R
SPKR3 = 1G_AudioBuzzer_AI_1027: Mistral Part No: 130014060027-R
A1 = 4P_LCD_WVGA_7in_wCapTouchOSD: Mistral Part No: 160014050038-R
FID1-FID6 = Fiducial
H1 = uSD_card: Memory Card microSD™ 16GB Class 10 MLC; DescriptiveText: Memory Card microSD™ 16GB Class 10 MLC; Descriptive_Text: Memory Card microSD™ 16GB Class 10 MLC; Mfr: ATP Electronics, Inc.
H2 = SD_card_Adapter: DescriptiveText: Adapter Connector Secure Digital - microSD To Secure Digital - SD; Descriptive_Text: Adapter Connector Secure Digital - microSD To Secure Digital - SD; Mfr: Seeed Technology Co., Ltd
H3 = RJ45_Cable: DescriptiveText: Modular Cable Plug to Plug 8p8c (RJ45, Ethernet) 7.00' (2.12m) Unshielded
H4 = USB_Cable: USB 2.0 Cable A Male to Micro B Male 3.28' (1.00m) Shielded; DescriptiveText: USB 2.0 Cable A Male to Micro B Male 3.28' (1.00m) Shielded; Mfr: Molex, LLC; Mfr_name: Molex, LLC
H5 = UART_Cable: DescriptiveText: D-Sub Cable Assembly DB09 Beige, Individual (Round) 9.84' (3.00m) Receptacle, Female Sockets to Receptacle, Female Sockets Shielded
LBL1 = THT-14-423-10: Serail Number Label; DescriptiveText: Serail Number Label
LOGO1 LOGO4 = TI_Logo
LOGO3 = FCC_disclaimer
M6 M7 M44 = 2H_Shunt0.1in: Mistral Part No: M160016080003
M8-M11 M14 M15 = 2M_RubberFeet_screwno4: Mistral Part No: 160015040003
M12 M13 M20-M23 M34-M37 = 2M_Screw_4-40_1_4: Mfr: APM Hexseal; MfrNum: R4-40X1/4 2701; Mistral Part No: M160016080004
M16-M19 M30 M31 = 2M_Standoff4-40x1_4x5_8Alum: Mistral Part No: M160016080005
M24 M25 M32 M33 = 2M_Screw_4-40_5_8: Mfr: APM Hexseal; MfrNum: R4-40X5/8 2701; Mistral Part No: M160016080006
M26 M27 M42 M43 = 2M_Washer_4-40_steel: Mistral Part No: M160016080007
M28 M29 = 2M_HexNut_4-40_steel: DescriptiveText: #4-40 Hex Nut 0.250" (6.35mm) 1/4" Stainless Steel; Mfr: Keystone; MfrNum: 9605; Mistral Part No: M160016080008
M38 M39 = 2M_AM43xxEVM_7inLCDMntBracket: Mistral Part No: 160014070001
M45 M46 = 2M_Screw_4-40_5_8: DescriptiveText: MACHINE SCREW PAN PHILLIPS 4-40; Mfr: Keystone; MfrNum: 9901; Mistral Part No: M160016080009
MH1-MH4 = MH
MH5-MH8 = MH1
PCB1 = 3K_AM438xePOSEVMBarePCB: Mistral Part No: FY170386000102; Version: 1.2
PCB2 = 4P_CameraBoardAssembledPCB
PCB3 = PCB3
PCB4 = PCB4
ZZ1-ZZ9 = AssemblyNoteLabel_0

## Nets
DGND: BT1.2(Neg) C3.2 C4.2 C5.2 C12.2 C69.2 C70.2 C71.2 C72.2(NEG) C73.2 C74.2(NEG) C76.2 C77.2 C78.2 C79.2 C80.2 C81.2 C82.2 C83.2 C84.2 C85.2 C86.2 C87.2 C88.2 C89.2 C90.2 C91.2 C92.2 C93.2 C94.2 C95.2 C96.2 C97.2 C120.2 C121.2 C122.2 C123.2 C406.2(NEG) C420.2 C439.2 C440.2 C464.2 D2.2(ANODE) D3.1(Cathode) D22.2(ANODE) J3.2 J3.3 J4.9 J4.15 J4.16 J6.4 J38.39 J38.40 J88.5 J88.6 Q11.S(SOURCE) R62.1(P1) R63.2(P2) R66.1(P1) R69.1(P1) R70.1(P1) R508.1(P1) R612.1(P1) R615.1(P1) R685.1(P1) R686.1(P1) SW1.1 SW1.2 SW2.1 SW2.2 SW3.M1 SW3.M2 SW4.1 SW4.2 SW8.1 SW8.2 TP9.1 TP10.1 TP11.1 TP12.1 U1.AD4(VSS_RTC) U2.TPAD(GNDP) U3.B4(SYNC) U3.C1(PGND) U3.C2(PGND) U3.C3(GND) U3.D3(GND) U3.E4(GND) U41.13(GND) U41.25(GND) U41.36(GND) U41.48(GND) U80.3(GND) ; also on sheet 1 2 4 5 7 8 9 10 11 13 14 15 16 17 18 19 20 21 22 23 24 25 26
GND_OSC: C1.2 C2.2 J98.2 J98.3 J98.4 J98.5 ; also on sheet 21
V1_0BAT: J95.2 R693.1(P1) ; also on sheet 21
V1_8BAT: J96.2 R40.2(P2) R390.1(P1) ; also on sheet 21 22
V1_8D: R49.1(P1) ; also on sheet 2 3 18 19
V1_8LPDDR2_EN: R627.1(P1) U2.11(GPIO1) ; also on sheet 16
V3_3D: C12.1 C120.1 C121.1 C122.1 C123.1 J6.1 J38.1 R1.2(P2) R5.2(P2) R41.2(P2) R50.2(P2) R51.2(P2) R55.1(P1) R61.1(P1) R64.2(P2) R144.2(P2) R145.2(P2) R146.2(P2) R439.2(P2) R611.2(P2) R628.2(P2) R629.2(P2) R692.1(P1) R717.2(P2) U41.12(VCC) U41.34(VCC) U41.37(VCC) U41.39(VCC) ; also on sheet 1 2 4 5 7 8 9 10 11 13 15 17 18 19 20 21 22 23 24 25 26
V5_0D: C92.1 C93.1 C94.1 R65.2(P2) U2.32(IN_LS2) U3.E1(VOUT) U3.E2(VOUT) ; also on sheet 5 10
V5_0D_EN: R64.1(P1) U3.A4(EN)
VBAT: C76.1 C78.1 C80.1 C83.1 C85.1 C86.1 C95.1 C96.1 C406.1(POS) J4.2 J4.4 J38.2 R38.2(P2) R39.2(P2) R59.2(P2) R507.2 R549.1(P1) U2.1(IN_DCDC1) U2.5(IN_LDO1) U2.12(IN_DCDC4) U2.27(IN_BU) U2.36(IN_BIAS) U2.37(IN_DCDC3) U2.43(IN_DCDC2) U3.A1(VIN) U3.A2(VIN) ; also on sheet 1 2 4 5 7 14 15 16 19 24
VBAT1_SW: TP42.1 U2.7(LS3)
VINT_LDO: C420.1 C464.1 R627.2(P2) R675.2(P2) U2.35(INT_LDO) U80.5(VCC)
AM438X_AIN7: R67.1(P1) ; also on sheet 3
AM438X_GPMC_ADVN_ALE: R151.2(P2) U1.A9(GPMC_ADVN_ALE) ; also on sheet 26
AM438X_GPMC_BE0N_CLE: R150.2(P2) U1.C10(GPMC_BE0N_CLE) ; also on sheet 26
AM438X_GPMC_CS0n: R149.2(P2) U1.A8(GPMC_CS0n) ; also on sheet 26
AM438X_GPMC_OEN_REN: R148.2(P2) U1.E10(GPMC_OEN_REN) ; also on sheet 26
AM438X_GPMC_WAIT0: R147.2(P2) U1.A2(GPMC_WAIT0)
AM438X_GPMC_WEN: R152.2(P2) U1.D10(GPMC_WEN/GPIO) ; also on sheet 26
AM438X_GPMC_WPn: R153.2(P2) R611.1(P1) R612.2(P2) ; also on sheet 19
AM438X_I2C0_SCL: R52.1(P1) R56.2(P2) U1.Y22(I2C_SCL0) ; also on sheet 18
AM438X_I2C0_SDA: R53.1(P1) R57.2(P2) U1.AB24(I2C_SDA0) ; also on sheet 18
AM438X_NAND_AD0: R136.2(P2) U1.B5(GPMC_AD0)
AM438X_NAND_AD1: R137.2(P2) U1.A5(GPMC_AD1)
AM438X_NAND_AD2: R138.2(P2) U1.B6(GPMC_AD2)
AM438X_NAND_AD3: R139.2(P2) U1.A6(GPMC_AD3)
AM438X_NAND_AD4: R140.2(P2) U1.B7(GPMC_AD4)
AM438X_NAND_AD5: R141.2(P2) U1.A7(GPMC_AD5)
AM438X_NAND_AD6: R142.2(P2) U1.C8(GPMC_AD6)
AM438X_NAND_AD7: R143.2(P2) U1.B8(GPMC_AD7)
AM438X_NMIn: R7.1(P1) R44.1(P1) U1.G25(NMIn)
AM438X_OSC0_IN: R706.1(P1) R713.1(P1) U1.C25(OSC0_IN)
AM438X_OSC0_OUT: R3.1(P1) U1.B25(OSC0_OUT)
AM438X_PMIC_IN_nCC: R48.1(P1) ; also on sheet 22
AM438X_PMIC_PFO: R60.1(P1) R589.1(P1)
AM438X_PMIC_PGOOD: C3.1 R1.1(P1) R13.2(P2) R45.1(P1) R616.2(P2) U80.2(A) ; also on sheet 24
AM438X_PORZn: R13.1(P1) U1.Y23(PORZn) ; also on sheet 8
AM438X_STATUS_LED0: J38.3 U1.B9(GPMC_CS1n/GPIO) ; also on sheet 14
AM438X_STATUS_LED1: J38.5 U1.F10(GPMC_CS2n/GPIO) ; also on sheet 14 23
AM438X_STATUS_LED2: J38.21 U1.AB25(CAM1_WEN) ; also on sheet 14
AM438X_STATUS_LED3: R665.1(P1) ; also on sheet 14
AM438X_UART3_RTSN: R71.1(P1) ; also on sheet 19
AM438X_VDDS: R72.1(P1) ; also on sheet 18 21
AM438X_WAKEUP1: R43.1(P1) ; also on sheet 22
BAT_HDQ: J4.13 R71.2(P2)
BUZZER_N: Q11.D(DRAIN) SPKR3.2(NEG-)
BUZZER_P: R507.1 SPKR3.1(POS+)
GP_I2C_SCL: J6.2 R52.2(P2) ; also on sheet 2 4 7 11
GP_I2C_SDA: J6.3 R53.2(P2) ; also on sheet 2 4 7 11
GPIO2: J38.7 R680.2(P2) U1.C3(GPMC_A0/GPIO)
GPIO4: J38.11 R663.2(P2) R664.2(P2) U1.C6(GPMC_A2/GPIO)
GPIO5: J38.13 R665.2(P2) R667.2(P2) U1.A4(GPMC_A3/GPIO)
GPIO6: J38.15 R589.2(P2) U1.D16(GMII1_COL/GPIO)
GPIO8: J38.19 R662.2(P2) R676.2(P2) U1.AB18(CAM0_DATA1)
GPIO10: J38.23 R531.2(P2) U1.AC25(CAM1_FIELD)
GPIO11: J38.25 R628.1(P1) R671.2(P2) U1.N23(JTAG_EMU0)
GPIO12: J38.27 R629.1(P1) R672.2(P2) U1.T24(JTAG_EMU1)
GPIO13: J38.29 R654.2(P2) U1.N20(SPI2_SCLK)
GPIO14: J38.31 R650.2(P2) R656.2(P2) U1.P22(SPI2_D0)
GPIO15: J38.33 R646.2(P2) R657.2(P2) U1.P20(SPI2_D1)
GPIO16: J38.35 R614.2(P2) U1.T23(SPI2_CS0)
GPMC_A0/GPIO: R680.1(P1) ; also on sheet 2
HDMI_INTn: R663.1(P1) ; also on sheet 5
JTAG_EMU0: R671.1(P1) ; also on sheet 8
JTAG_EMU1: R672.1(P1) ; also on sheet 8
LOWPOWERn: R692.2(P2) TP41.1 U1.H20(CLKREQ) ; also on sheet 9
NAND_ADVN_ALE: R151.1(P1) U41.17(ALE)
NAND_BE0n_CLE: R150.1(P1) U41.16(CLE)
NAND_CSn: R144.1(P1) R149.1(P1) U41.9(\\~{CE})
NAND_D0: R136.1(P1) U41.29(I/O0)
NAND_D1: R137.1(P1) U41.30(I/O1)
NAND_D2: R138.1(P1) U41.31(I/O2)
NAND_D3: R139.1(P1) U41.32(I/O3)
NAND_D4: R140.1(P1) U41.41(I/O4)
NAND_D5: R141.1(P1) U41.42(I/O5)
NAND_D6: R142.1(P1) U41.43(I/O6)
NAND_D7: R143.1(P1) U41.44(I/O7)
NAND_OEn: R148.1(P1) U41.8(\\~{R}E)
NAND_WAIT: R145.1(P1) R147.1(P1) U41.7(R~{/B})
NAND_WEn: R152.1(P1) U41.18(\\~{W}E)
NAND_WPn: R146.1(P1) R153.1(P1) U41.19(\\~{W}P)
PB_INTERRUPT: C4.1 R5.1(P1) R7.2(P2) SW1.3 SW1.4
PMIC_AC_DET: J4.14 R38.1(P1) U2.9(AC_DET)
PMIC_I2C_SCL: R50.1(P1) R56.1(P1) U2.3(SCL)
PMIC_I2C_SDA: R51.1(P1) R57.1(P1) U2.2(SDA)
PMIC_IN_nCC: R48.2(P2) U2.18(IN_nCC)
PMIC_INTn: R41.1(P1) R44.2(P2) U2.45(INTn)
PMIC_L5: L1.1 U2.20(L5)
PMIC_L6: L2.1 U2.23(L6)
PMIC_LDO1: C84.1 R49.2(P2) U2.4(LDO1)
PMIC_PFI: R59.1(P1) R62.2(P2) U2.16(PFI)
PMIC_PFOn: R60.2(P2) R61.2(P2) U2.10(PFOn)
PMIC_PGOOD: R45.2(P2) U2.8(PGOOD)
PMIC_PGOODBU: R47.2(P2) U2.19(PGOOD_BU)
PMIC_PWR_EN: J93.1 ; also on sheet 22
PMIC_SYS_BU: C81.1 U2.24(SYS_BU)
PMIC_WAKEUPn: R40.1(P1) R43.2(P2) U2.40(WAKEUPn)
PMU_PORZn: J4.5 R47.1(P1) ; also on sheet 22
PRINT_eHRPWM1_A: R664.1(P1) ; also on sheet 24
PRINT_eHRPWM1_B: R667.1(P1) ; also on sheet 24
PRINT_SPI_CLK: R654.1(P1) ; also on sheet 24
PRINT_SPI_CSn: R614.1(P1) ; also on sheet 24
PRINT_SPI_MISO: R656.1(P1) ; also on sheet 24
PRINT_SPI_MOSI: R657.1(P1) ; also on sheet 24
PRINTER_GPIO0: R662.1(P1) ; also on sheet 24
PWRTST1: J4.7 U2.28(RSV1)
PWRTST2: J4.8 U2.29(RSV2)
RS232_1_EN: J38.17 R615.2(P2) U1.C16(GMII1_TXD3/GPIO) ; also on sheet 7 17
SDMMC0_WP: R646.1(P1) ; also on sheet 25
SYS_RESETn: R24.2(P2) ; also on sheet 2 4 9 11 26
SYS_WARMRESETn: R4.2(P2) R439.1(P1) R534.1(P1) R719.2(P2) ; also on sheet 8 24
TEST_GPIO17: J38.37 U1.A15(GMII1_RXDV/GPIO) ; also on sheet 24
TSC_INTn: J38.9 U1.C5(GPMC_A1/GPIO) ; also on sheet 4
USB0_VBUS_DET: R676.1(P1) ; also on sheet 10
USB5V_FB: R65.1(P1) R66.2(P2) U3.E3(FB)
VDCDC1: C87.1 L3.2 U2.47(FB1) ; also on sheet 18
VDCDC2: C88.1 L4.2 U2.41(FB2) ; also on sheet 18
VDCDC3: C89.1 L5.2 R54.2(P2) U2.31(IN_LS1) U2.39(FB3) ; also on sheet 18
VDCDC4: C90.1 C439.1 C440.1 R55.2(P2) U2.15(DCDC4)
VLS1: R58.1(P1) ; also on sheet 18
VPMIC_LS1: C91.1 R58.2(P2) U2.30(LS1)
VPMIC_LS2: R68.2(P2) U2.33(LS2)
VPP_CTRL: R650.1(P1) ; also on sheet 21
VPWR_IN: C69.1 C70.1 C71.1 C72.1(POS) C73.1 C74.1(POS) J4.1 J4.3 R37.2(P2) R549.2(P2) SW3.2 TP5.1 U2.6(IN_LS3)
VPWRIN_FUSED: D2.1(CATHODE) F1.2 SW3.1
VPWRIN_JCK: D1.2(ANODE) J3.1
VPWRIN_PREFUSE: D1.1(CATHODE) F1.1
VUSB_VBUS0: R68.1(P1) ; also on sheet 10
N10223382: C2.1 R2.2(P2) R713.2(P2) Y1.3
N10223390: C1.1 R2.1(P1) R3.2(P2) Y1.1
N11290910: R4.1(P1) U1.G22(RESETIN_OUTn)
N13731332: D22.1(CATHODE) L6.1 U2.13(L4A)
N13731348: L5.1 U2.38(L3)
N13731364: L4.1 U2.42(L2)
N13731380: L3.1 U2.48(L1)
N13731441: C79.1 J95.1 L1.2 R693.2(P2) U2.21(FB5)
N13731460: C82.1 J96.1 L2.2 R390.2(P2) U2.22(FB6)
N13732491: L6.2 U2.14(L4B)
N13761460: R39.1(P1) SW4.3 SW4.4 U2.44(PB)
N13764462: C77.1 J13.2 U2.25(CC)
N13764557: BT1.1(Pos) J5.1 R46.2(P2)
N13765581: L7.1 U3.B1(L1) U3.B2(L1)
N13765601: L7.2 U3.D1(L2) U3.D2(L2)
N13765621: C97.1 U3.A3(VINA) U3.B3(VINA1) U3.C4(~{PS}) U3.D4(VSEL)
N13766448: R54.1(P1) TP8.1 U2.34(GPO2)
N13766683: R63.1(P1) U2.17(DC34_SEL)
N14048473: Q11.G(GATE) R508.2(P2) R531.1(P1)
N14105322: J5.2 J13.1 R46.1(P1)
N14353527: J93.2 U2.46(PWR_EN)
N14355021: D3.2(Anode) R37.1(P1)
N17870609: J88.1 U1.AB9(TEST_TP0)
N17870629: J88.3 U1.AC7(TEST_TP2)
N17870635: J88.2 U1.W10(TEST_TP1)
N17870639: J88.4 U1.Y6(TEST_TP3)
N18608778: J4.11 R67.2(P2)
N19065641: J93.3 R675.1(P1)
N19134448: R616.1(P1) SW8.3 SW8.4
N19750152: C5.1 R533.2(P2) R719.1(P1)
N19750155: R533.1(P1) SW2.3 SW2.4
N19750452: R24.1(P1) R534.2(P2) U80.4(Y)
N20177044: R72.2(P2) U1.AE2(RTC_KALDO_EN)
N20177053: R69.2(P2) U1.AE6(VSS)
N20177055: R70.2(P2) U1.AE3(VSS)
N20460297: R685.2(P2) U1.AD10(TM_TESTOUT)
N20460313: R686.2(P2) U1.AD11(CTPM_TESTOUT)
N20541228: J98.1 R706.2(P2)
N20948781: R717.1(P1) U2.26(GPIO3)

Not connected (* = marked no-connect by the designer): J4 6* 10* 12*; J38 4* 6* 8* 10* 12* 14* 16* 18* 20* 22* 24* 26* 28* 30* 32* 34* 36* 38*; SW3 3*; U1 AD6(RSV)* AE4(OSC1_OUT)* AE5(OSC1_IN)* AE9(RSV)* H19(RSV)*; U41 1(NC-1)* 2(NC-2)* 3(NC-3)* 4(NC-4)* 5(NC-5)* 6(NC-6)* 10(NC-7)* 11(NC-8)* 14(NC-9)* 15(NC-10)* 20(NC-11)* 21(NC-12)* 22(NC-13)* 23(NC-14)* 24(NC-15)* 26(NC_IO8)* 27(NC_IO9)* 28(NC_IO10)* 33(NC_IO11)* 35(NC16)* 38(NC17)* 40(NC_IO12)* 45(NC_IO13)* 46(NC_IO14)* 47(NC_IO15)*; U80 1(NC); Y1 2(NC0)* 4(NC1)*

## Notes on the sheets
sheet 27
- NAND Memory
sheet 29
- HARDWARE SCHEMATICS
- MOUNTING HOLES
- STANDOFFs
- FIDUCIALS
- MSR
- LCD
- LOGOs & LABELs
- KIT CONTENTS
- MicroSD CARD and Adapter
- ETHERNET CABLE
- USB CABLE
- UART CABLE
- Board Serial No.
sheet 30
- Main Power Input
- Battery Board
  Connector
- Connect Shunt between J4.14 and J4.16
  if Battery is not present
- Connect Shunt between J13.1 and J13.2
- Coin Cell
- Connect Shunt between J93.2 and J93.3
sheet 31
- External Clock IN
- Processor Control/Clock
- Hard
  Reset Switch
- Warm Reset Switch
- User Interrupt Switch
- RTC Module - Not used
